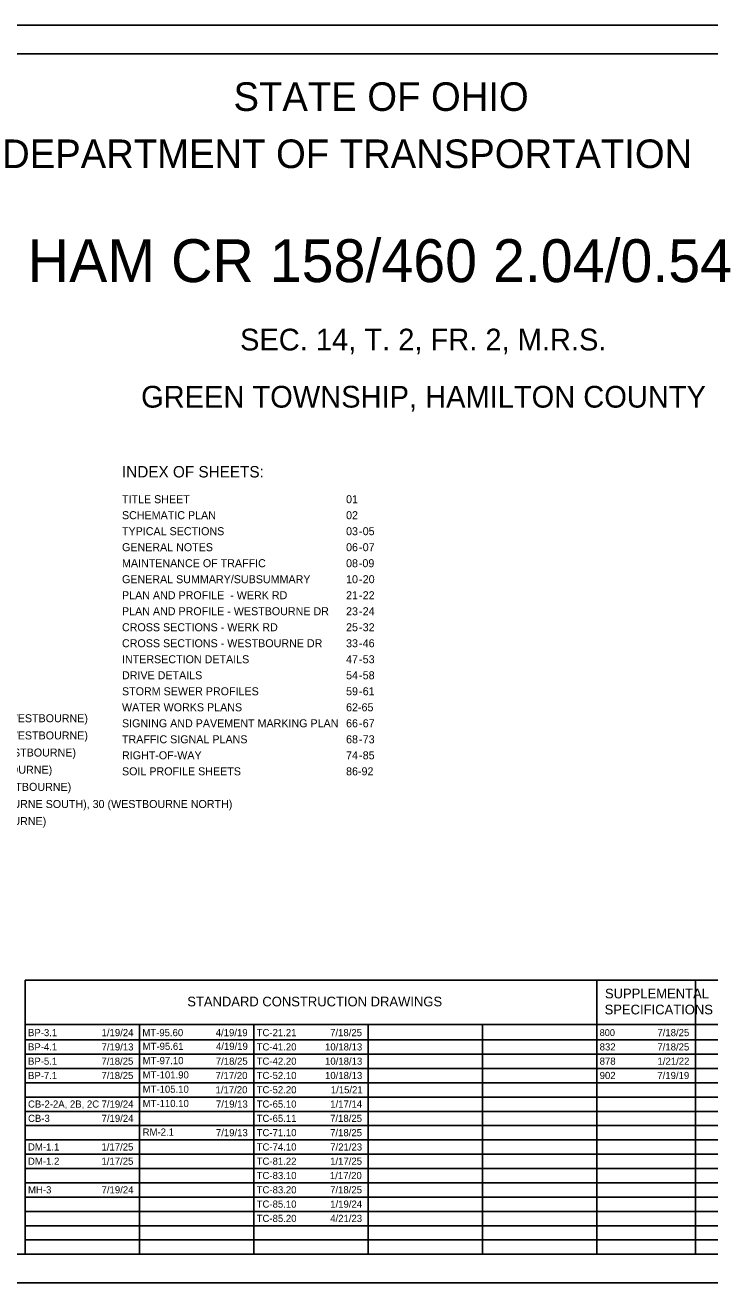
# Model space of a CAD drawing. Extents: x 0 to 34, y 0 to 22.
# Drawn here: x 10.15 to 22.13, y 0 to 22 of the extents above; entities that cross this region are included whole.
import ezdxf

# ---------------------------------------------------------------- set-up
doc = ezdxf.new("R2010")
doc.units = 0
for name, color, linetype in [('Default', 7, 'Continuous'), ('SH_Border', 7, 'Continuous'), ('SH_Cut_Line', 7, 'Continuous'), ('SH_Data', 7, 'Continuous'), ('SH_Text', 7, 'Continuous')]:
    doc.layers.add(name, color=color, linetype=linetype)

msp = doc.modelspace()

# ---------------------------------------------------------------- linework, layer by layer
at = {"layer": 'SH_Border'}
msp.add_lwpolyline([(1.5, 21.5), (33.5, 21.5), (33.5, 0.5), (1.5, 0.5)], close=True, dxfattribs=at)
at = {"layer": 'SH_Cut_Line'}
msp.add_lwpolyline([(0, 0), (34, 0), (34, 22), (0, 22)], close=True, dxfattribs=at)
at = {"layer": 'SH_Data'}
for p, q in [((10.15, 5.292), (23.6, 5.292)), ((10.15, 0.5), (10.15, 5.292)), ((20.15, 0.5), (20.15, 5.292)), ((21.875, 0.5), (21.875, 5.292)), ((10.15, 4.521), (23.6, 4.521)), ((12.15, 0.5), (12.15, 4.521)), ((14.15, 0.5), (14.15, 4.521)), ((16.15, 0.5), (16.15, 4.521)), ((18.15, 0.5), (18.15, 4.521)), ((10.15, 4.25), (23.6, 4.25)), ((10.15, 4), (23.6, 4)), ((10.15, 3.75), (23.6, 3.75)), ((10.15, 3.5), (23.6, 3.5)), ((10.15, 3.25), (23.6, 3.25)), ((10.15, 3), (23.6, 3)), ((10.15, 2.75), (23.6, 2.75)), ((10.15, 2.5), (23.6, 2.5)), ((10.15, 2.25), (23.6, 2.25)), ((10.15, 2), (23.6, 2)), ((10.15, 1.75), (23.6, 1.75)), ((10.15, 1.5), (23.6, 1.5)), ((10.15, 1.25), (23.6, 1.25)), ((10.15, 1), (23.6, 1)), ((10.15, 0.75), (23.6, 0.75))]:
    msp.add_line(p, q, dxfattribs=at)

# ---------------------------------------------------------------- texts
at = {"layer": 'Default'}
for s, height, p in [('TITLE SHEET', 0.14, (11.844, 13.638)), ('01', 0.14, (15.764, 13.638)), ('SCHEMATIC PLAN', 0.14, (11.844, 13.358)), ('02', 0.14, (15.764, 13.358)), ('TYPICAL SECTIONS', 0.14, (11.844, 13.078)), ('03', 0.14, (15.764, 13.078)), ('05', 0.14, (16.055, 13.078)), ('-', 0.14, (15.988, 13.078)), ('GENERAL NOTES', 0.14, (11.844, 12.798)), ('06', 0.14, (15.764, 12.798)), ('-', 0.14, (15.988, 12.798)), ('07', 0.14, (16.055, 12.798)), ('MAINTENANCE OF TRAFFIC', 0.14, (11.844, 12.518)), ('08', 0.14, (15.764, 12.518)), ('-09', 0.14, (15.988, 12.518)), ('GENERAL SUMMARY/SUBSUMMARY', 0.14, (11.844, 12.238)), ('10', 0.14, (15.764, 12.238)), ('20', 0.14, (16.055, 12.238)), ('-', 0.14, (15.988, 12.238)), ('PLAN AND PROFILE  - WERK RD', 0.14, (11.844, 11.958)), ('21', 0.14, (15.764, 11.958)), ('-', 0.14, (15.988, 11.958)), ('22', 0.14, (16.055, 11.958)), ('PLAN AND PROFILE - WESTBOURNE DR', 0.14, (11.844, 11.678)), ('23', 0.14, (15.764, 11.678)), ('-', 0.14, (15.988, 11.678)), ('24', 0.14, (16.055, 11.678)), ('CROSS SECTIONS - WERK RD', 0.14, (11.844, 11.398)), ('25', 0.14, (15.764, 11.398)), ('-', 0.14, (15.988, 11.398)), ('32', 0.14, (16.055, 11.398)), ('CROSS SECTIONS - WESTBOURNE DR', 0.14, (11.844, 11.118)), ('33', 0.14, (15.764, 11.118)), ('46', 0.14, (16.055, 11.118)), ('-', 0.14, (15.988, 11.118)), ('INTERSECTION DETAILS', 0.14, (11.844, 10.838)), ('47', 0.14, (15.764, 10.838)), ('-', 0.14, (15.988, 10.838)), ('53', 0.14, (16.055, 10.838)), ('DRIVE DETAILS', 0.14, (11.844, 10.558)), ('54', 0.14, (15.764, 10.558)), ('-', 0.14, (15.988, 10.558)), ('58', 0.14, (16.055, 10.558)), ('STORM SEWER PROFILES', 0.14, (11.844, 10.278)), ('59', 0.14, (15.764, 10.278)), ('61', 0.14, (16.055, 10.278)), ('-', 0.14, (15.988, 10.278)), ('SIGNING AND PAVEMENT MARKING PLAN', 0.14, (11.844, 9.718)), ('66', 0.14, (15.764, 9.718)), ('-', 0.14, (15.988, 9.718)), ('67', 0.14, (16.055, 9.718)), ('TRAFFIC SIGNAL PLANS', 0.14, (11.844, 9.438)), ('68', 0.14, (15.764, 9.438)), ('-', 0.14, (15.988, 9.438)), ('73', 0.14, (16.055, 9.438)), ('RIGHT-OF-WAY', 0.14, (11.844, 9.158)), ('74', 0.14, (15.764, 9.158)), ('85', 0.14, (16.055, 9.158)), ('-', 0.14, (15.988, 9.158)), ('BP-3.1', 0.125, (10.2, 4.315)), ('1/19/24', 0.125, (11.487, 4.315)), ('MT-95.60', 0.125, (12.2, 4.315)), ('4/19/19', 0.125, (13.484, 4.315)), ('TC-21.21', 0.125, (14.2, 4.315)), ('7/18/25', 0.125, (15.485, 4.315)), ('800', 0.12, (20.2, 4.317)), ('7/18/25', 0.125, (21.21, 4.315)), ('BP-4.1', 0.125, (10.2, 4.065)), ('7/19/13', 0.125, (11.487, 4.065)), ('MT-95.61', 0.125, (12.205, 4.075)), ('4/19/19', 0.125, (13.488, 4.075)), ('TC-41.20', 0.125, (14.2, 4.065)), ('10/18/13', 0.125, (15.396, 4.065)), ('832', 0.125, (20.2, 4.065)), ('7/18/25', 0.125, (21.21, 4.065)), ('BP-5.1', 0.125, (10.2, 3.815)), ('7/18/25', 0.125, (11.485, 3.815)), ('MT-97.10', 0.125, (12.205, 3.825)), ('7/18/25', 0.125, (13.485, 3.815)), ('TC-42.20', 0.125, (14.2, 3.815)), ('10/18/13', 0.125, (15.396, 3.815)), ('878', 0.125, (20.2, 3.815)), ('1/21/22', 0.125, (21.212, 3.815)), ('BP-7.1', 0.125, (10.2, 3.565)), ('7/18/25', 0.125, (11.485, 3.565)), ('MT-101.90', 0.125, (12.205, 3.575)), ('7/17/20', 0.125, (13.481, 3.565)), ('TC-52.10', 0.125, (14.2, 3.565)), ('10/18/13', 0.125, (15.396, 3.565)), ('902', 0.125, (20.2, 3.565)), ('7/19/19', 0.125, (21.209, 3.565)), ('MT-105.10', 0.125, (12.205, 3.325)), ('1/17/20', 0.125, (13.481, 3.315)), ('TC-52.20', 0.125, (14.2, 3.315)), ('1/15/21', 0.125, (15.497, 3.315)), ('CB-2-2A, 2B, 2C', 0.125, (10.2, 3.065)), ('7/19/24', 0.125, (11.487, 3.065)), ('MT-110.10', 0.125, (12.205, 3.075)), ('7/19/13', 0.125, (13.487, 3.065)), ('TC-65.10', 0.125, (14.2, 3.065)), ('1/17/14', 0.125, (15.487, 3.065)), ('CB-3', 0.125, (10.2, 2.815)), ('7/19/24', 0.125, (11.487, 2.815)), ('TC-65.11', 0.125, (14.2, 2.815)), ('7/18/25', 0.125, (15.485, 2.815)), ('RM-2.1', 0.125, (12.205, 2.575)), ('7/19/13', 0.125, (13.487, 2.565)), ('TC-71.10', 0.125, (14.2, 2.565)), ('7/18/25', 0.125, (15.485, 2.565)), ('DM-1.1', 0.125, (10.2, 2.315)), ('1/17/25', 0.125, (11.485, 2.315)), ('TC-74.10', 0.125, (14.2, 2.315)), ('7/21/23', 0.125, (15.487, 2.315)), ('DM-1.2', 0.125, (10.2, 2.065)), ('1/17/25', 0.125, (11.485, 2.065)), ('TC-81.22', 0.125, (14.2, 2.065)), ('1/17/25', 0.125, (15.485, 2.065)), ('TC-83.10', 0.125, (14.2, 1.815)), ('1/17/20', 0.125, (15.481, 1.815)), ('MH-3', 0.125, (10.2, 1.565)), ('7/19/24', 0.125, (11.487, 1.565)), ('TC-83.20', 0.125, (14.2, 1.565)), ('7/18/25', 0.125, (15.485, 1.565)), ('TC-85.10', 0.125, (14.2, 1.315)), ('1/19/24', 0.125, (15.487, 1.315)), ('TC-85.20', 0.125, (14.2, 1.065)), ('4/21/23', 0.125, (15.487, 1.065))]:
    msp.add_text(s, height=height, dxfattribs=at).set_placement(p)
at = {"layer": 'SH_Text'}
for s, height, p in [('STATE OF OHIO', 0.5, (13.795, 20.5)), ('DEPARTMENT OF TRANSPORTATION', 0.5, (9.747, 19.5)), ('HAM CR 158/460 2.04/0.54', 0.75, (10.195, 17.505)), ('SEC. 14, T. 2, FR. 2, M.R.S.', 0.38, (13.909, 16.31)), ('GREEN TOWNSHIP, HAMILTON COUNTY', 0.38, (12.178, 15.31)), ('INDEX OF SHEETS:', 0.2, (11.844, 14.088)), ('WATER WORKS PLANS', 0.14, (11.844, 9.998)), ('62-65', 0.14, (15.764, 9.998)), ('13,700 (WERK), 14,300 (WESTBOURNE)', 0.14, (7.742, 9.806)), ('18,800 (WERK), 19,500 (WESTBOURNE)', 0.14, (7.742, 9.506)), ('1,010 (WERK), 1,030 (WESTBOURNE)', 0.14, (7.742, 9.206)), ('.53 (WERK), .58 (WESTBOURNE)', 0.14, (7.742, 8.906)), ('SOIL PROFILE SHEETS ', 0.14, (11.844, 8.878)), ('86-92', 0.14, (15.764, 8.878)), ('0.5% (WERK), 0.5% (WESTBOURNE)', 0.14, (7.742, 8.606)), ('35 (WERK), 35 (WESTBOURNE SOUTH), 30 (WESTBOURNE NORTH)', 0.14, (7.742, 8.306)), ('35 (WERK), 35 (WESTBOURNE)', 0.14, (7.742, 8.006)), ('SUPPLEMENTAL', 0.17, (20.293, 4.976)), ('STANDARD CONSTRUCTION DRAWINGS', 0.17, (12.986, 4.836)), ('SPECIFICATIONS', 0.17, (20.287, 4.696))]:
    msp.add_text(s, height=height, dxfattribs=at).set_placement(p)

doc.saveas('drawing.dxf')
